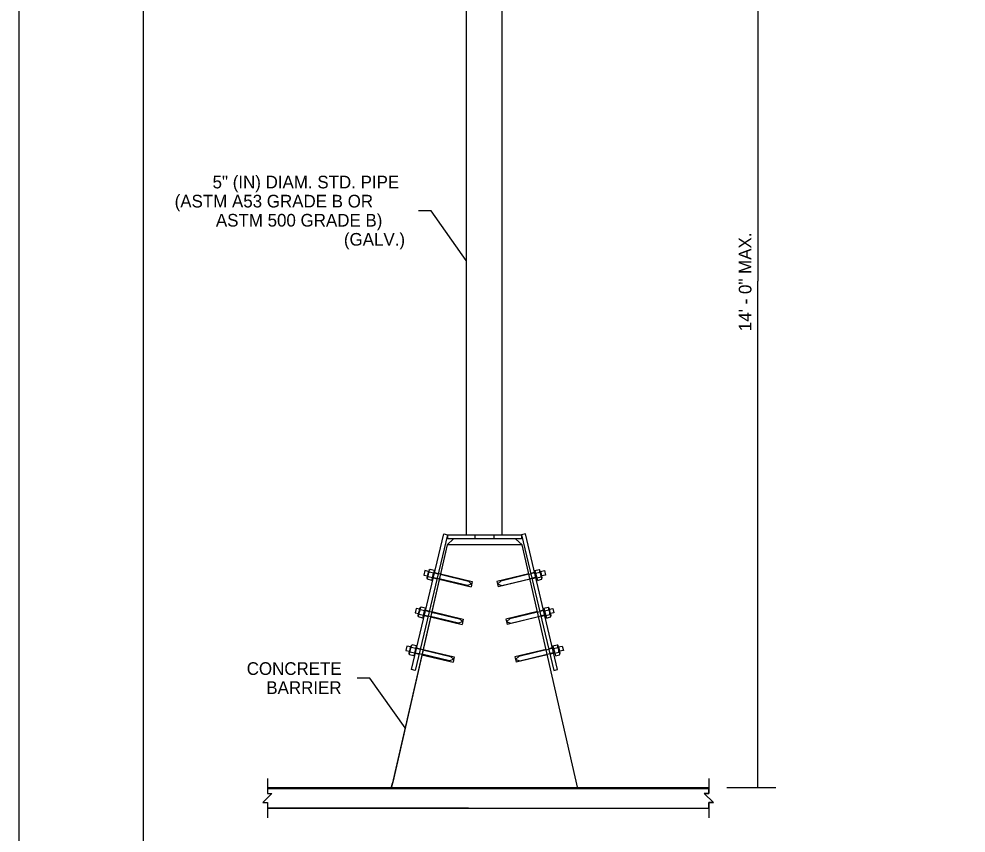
# Model space of a CAD drawing. Extents: x 99988 to 100172, y 99995 to 100047.
# Drawn here: x 99999.31 to 100004.55, y 100001.43 to 100005.94 of the extents above; entities that cross this region are included whole.
import ezdxf

# ---------------------------------------------------------------- set-up
doc = ezdxf.new("R2010")
doc.units = 0
for name, color, linetype in [('Level 1', 7, 'Continuous'), ('Level 10', 7, 'Continuous'), ('Level 12', 7, 'Continuous'), ('Level 15', 7, 'Continuous'), ('Level 18', 7, 'Continuous'), ('Level 20', 7, 'Continuous'), ('Level 8', 7, 'Continuous'), ('SH_GI_PlotLimits', 7, 'Continuous'), ('SH_GI_SheetBorder', 7, 'Continuous')]:
    doc.layers.add(name, color=color, linetype=linetype)

msp = doc.modelspace()

# ---------------------------------------------------------------- linework, layer by layer
at = {"layer": 'Level 1'}
msp.add_line((100000.6865, 100001.681), (100003.128, 100001.681), dxfattribs=at)
for points in [[(100001.7992, 100001.571), (100000.6865, 100001.571)], [(100000.6865, 100001.571), (100003.128, 100001.571)]]:
    msp.add_lwpolyline(points, dxfattribs=at)
at = {"layer": 'Level 10'}
for p, q in [((100001.7865, 100006.8371), (100001.7865, 100003.0807)), ((100001.9852, 100003.0795), (100001.9852, 100006.8371))]:
    msp.add_line(p, q, dxfattribs=at)
at = {"layer": 'Level 12'}
for p, q in [((100001.6841, 100003.0822), (100002.0912, 100003.0822)), ((100001.6841, 100003.0822), (100002.0912, 100003.0822)), ((100001.6841, 100003.0607), (100001.6841, 100003.0822)), ((100002.0912, 100003.0607), (100001.6841, 100003.0607)), ((100001.8341, 100003.0822), (100001.8341, 100003.0607)), ((100001.9412, 100003.0607), (100001.8341, 100003.0607)), ((100001.9412, 100003.0607), (100001.9412, 100003.0822)), ((100002.0912, 100003.0822), (100002.0912, 100003.0607))]:
    msp.add_line(p, q, dxfattribs=at)
for points in [[(100001.683, 100003.0834), (100001.5046, 100002.3333), (100001.4838, 100002.3382), (100001.6621, 100003.0884)], [(100002.0923, 100003.0834), (100002.2707, 100002.3333), (100002.2915, 100002.3382), (100002.1132, 100003.0884)]]:
    msp.add_lwpolyline(points, close=True, dxfattribs=at)
at = {"layer": 'Level 15'}
for p, q in [((100003.3984, 100007.2852), (100003.3984, 100004.4852)), ((100003.3984, 100001.6852), (100003.3984, 100004.4852)), ((100003.228, 100001.6852), (100003.4984, 100001.6852))]:
    msp.add_line(p, q, dxfattribs=at)
for points in [[(100001.7865, 100004.6), (100001.5917, 100004.8754), (100001.5217, 100004.8754)], [(100001.4482, 100002.0153), (100001.2534, 100002.2907), (100001.1834, 100002.2907)], [(100000.6865, 100001.7357), (100000.6865, 100001.6525), (100000.7118, 100001.6525), (100000.6612, 100001.602), (100000.6865, 100001.602), (100000.6865, 100001.5188)], [(100003.128, 100001.7357), (100003.128, 100001.6525), (100003.1027, 100001.6525), (100003.1532, 100001.602), (100003.128, 100001.602), (100003.128, 100001.5188)]]:
    msp.add_lwpolyline(points, dxfattribs=at)
at = {"layer": 'Level 18'}
for p, q in [((100001.8019, 100003.0822), (100001.9733, 100003.0822)), ((100001.968, 100003.0822), (100001.9733, 100003.0822)), ((100001.5572, 100002.8851), (100001.5514, 100002.8608)), ((100001.5514, 100002.8608), (100001.5721, 100002.8558)), ((100001.5782, 100002.8801), (100001.5572, 100002.8851)), ((100001.6001, 100002.8491), (100001.605, 100002.848)), ((100001.605, 100002.848), (100001.6258, 100002.843)), ((100001.6062, 100002.8734), (100001.6107, 100002.8723)), ((100001.6107, 100002.8723), (100001.6316, 100002.8674)), ((100001.6426, 100002.8647), (100001.6316, 100002.8674)), ((100001.6426, 100002.8647), (100001.7983, 100002.8277)), ((100002.1328, 100002.8647), (100001.9771, 100002.8277)), ((100002.1328, 100002.8647), (100002.1438, 100002.8674)), ((100002.1647, 100002.8723), (100002.1438, 100002.8674)), ((100002.1705, 100002.848), (100002.1496, 100002.843)), ((100002.1692, 100002.8734), (100002.1647, 100002.8723)), ((100002.1753, 100002.8491), (100002.1705, 100002.848)), ((100002.1972, 100002.8801), (100002.2183, 100002.8851)), ((100002.224, 100002.8608), (100002.2033, 100002.8558)), ((100002.2183, 100002.8851), (100002.224, 100002.8608)), ((100001.6258, 100002.843), (100001.6371, 100002.8404)), ((100001.7925, 100002.8034), (100001.6371, 100002.8404)), ((100001.8135, 100002.8099), (100001.7925, 100002.8034)), ((100001.7983, 100002.8277), (100001.8141, 100002.8124)), ((100001.9771, 100002.8277), (100001.9613, 100002.8124)), ((100001.9619, 100002.8099), (100001.9829, 100002.8034)), ((100001.9829, 100002.8034), (100002.1384, 100002.8404)), ((100002.1384, 100002.8404), (100002.1496, 100002.843)), ((100001.51, 100002.6762), (100001.5042, 100002.6519)), ((100001.5042, 100002.6519), (100001.5233, 100002.6473)), ((100001.5289, 100002.6717), (100001.51, 100002.6762)), ((100001.5505, 100002.6407), (100001.5554, 100002.6395)), ((100001.5554, 100002.6395), (100001.5762, 100002.6346)), ((100001.5566, 100002.6649), (100001.5612, 100002.6639)), ((100001.5612, 100002.6639), (100001.582, 100002.6589)), ((100001.5948, 100002.6559), (100001.582, 100002.6589)), ((100001.5948, 100002.6559), (100001.7488, 100002.6193)), ((100002.1806, 100002.6559), (100002.0267, 100002.6193)), ((100002.1806, 100002.6559), (100002.1934, 100002.6589)), ((100002.2142, 100002.6639), (100002.1934, 100002.6589)), ((100002.22, 100002.6395), (100002.1992, 100002.6346)), ((100002.2188, 100002.6649), (100002.2142, 100002.6639)), ((100002.2249, 100002.6407), (100002.22, 100002.6395)), ((100002.2465, 100002.6717), (100002.2654, 100002.6762)), ((100002.2712, 100002.6519), (100002.2522, 100002.6473)), ((100002.2654, 100002.6762), (100002.2712, 100002.6519)), ((100001.5762, 100002.6346), (100001.5892, 100002.6315)), ((100001.743, 100002.5949), (100001.5892, 100002.6315)), ((100001.764, 100002.6015), (100001.743, 100002.5949)), ((100001.7488, 100002.6193), (100001.7646, 100002.604)), ((100002.0267, 100002.6193), (100002.0108, 100002.604)), ((100002.0114, 100002.6015), (100002.0324, 100002.5949)), ((100002.0324, 100002.5949), (100002.1862, 100002.6315)), ((100002.1862, 100002.6315), (100002.1992, 100002.6346)), ((100001.458, 100002.4682), (100001.4522, 100002.4438)), ((100001.4522, 100002.4438), (100001.4729, 100002.4389)), ((100001.479, 100002.4632), (100001.458, 100002.4682)), ((100001.5006, 100002.4323), (100001.5056, 100002.4311)), ((100001.5056, 100002.4311), (100001.5264, 100002.4262)), ((100001.5069, 100002.4565), (100001.5114, 100002.4555)), ((100001.5114, 100002.4555), (100001.5322, 100002.4505)), ((100001.547, 100002.447), (100001.5322, 100002.4505)), ((100001.547, 100002.447), (100001.699, 100002.4109)), ((100002.2284, 100002.447), (100002.0765, 100002.4109)), ((100002.2284, 100002.447), (100002.2432, 100002.4505)), ((100002.264, 100002.4555), (100002.2432, 100002.4505)), ((100002.2698, 100002.4311), (100002.249, 100002.4262)), ((100002.2686, 100002.4565), (100002.264, 100002.4555)), ((100002.2748, 100002.4323), (100002.2698, 100002.4311)), ((100002.2964, 100002.4632), (100002.3174, 100002.4682)), ((100002.3232, 100002.4438), (100002.3025, 100002.4389)), ((100002.3174, 100002.4682), (100002.3232, 100002.4438)), ((100001.5264, 100002.4262), (100001.5414, 100002.4226)), ((100001.6932, 100002.3866), (100001.5414, 100002.4226)), ((100001.7142, 100002.3931), (100001.6932, 100002.3866)), ((100001.699, 100002.4109), (100001.7148, 100002.3956)), ((100002.0765, 100002.4109), (100002.0606, 100002.3956)), ((100002.0612, 100002.3931), (100002.0822, 100002.3866)), ((100002.0822, 100002.3866), (100002.234, 100002.4226)), ((100002.234, 100002.4226), (100002.249, 100002.4262))]:
    msp.add_line(p, q, dxfattribs=at)
for centre, start, end in [((100001.8131, 100002.8113), 287.2722, 45.9747), ((100001.9623, 100002.8113), 134.0253, 252.7278), ((100001.7635, 100002.6029), 287.2722, 45.9747), ((100002.0119, 100002.6029), 134.0253, 252.7278), ((100001.7137, 100002.3945), 287.2722, 45.9747), ((100002.0617, 100002.3945), 134.0253, 252.7278)]:
    msp.add_arc(centre, 0.0015, start, end, dxfattribs=at)
at = {"layer": 'Level 20'}
for p, q in [((100001.5697, 100002.8455), (100001.572, 100002.8545)), ((100001.599, 100002.8448), (100001.5757, 100002.8507)), ((100001.5858, 100002.8912), (100001.5796, 100002.8851)), ((100001.6058, 100002.8717), (100001.5825, 100002.8775)), ((100001.6091, 100002.8853), (100001.5859, 100002.8911)), ((100001.5989, 100002.8445), (100001.6058, 100002.8719)), ((100001.6058, 100002.8717), (100001.599, 100002.8448)), ((100001.6091, 100002.8853), (100001.6058, 100002.8717)), ((100001.6091, 100002.8854), (100001.6091, 100002.8853)), ((100001.6113, 100002.8747), (100001.6322, 100002.8698)), ((100001.6432, 100002.8672), (100001.8194, 100002.8253)), ((100002.1322, 100002.8672), (100001.956, 100002.8253)), ((100002.1641, 100002.8747), (100002.1433, 100002.8698)), ((100002.1663, 100002.8853), (100002.1895, 100002.8911)), ((100002.1663, 100002.8854), (100002.1664, 100002.8853)), ((100002.1663, 100002.8853), (100002.1697, 100002.8717)), ((100002.1765, 100002.8445), (100002.1696, 100002.8719)), ((100002.1697, 100002.8717), (100002.193, 100002.8775)), ((100002.1697, 100002.8717), (100002.1764, 100002.8448)), ((100002.1764, 100002.8448), (100002.1997, 100002.8507)), ((100002.1896, 100002.8912), (100002.1958, 100002.8851)), ((100002.2057, 100002.8455), (100002.2034, 100002.8545)), ((100001.5956, 100002.8313), (100001.5723, 100002.8371)), ((100001.599, 100002.8448), (100001.5956, 100002.8313)), ((100001.5956, 100002.8313), (100001.5989, 100002.8445)), ((100001.6044, 100002.8456), (100001.6252, 100002.8406)), ((100001.6365, 100002.8379), (100001.8125, 100002.7961)), ((100001.8194, 100002.8253), (100001.8125, 100002.7961)), ((100001.956, 100002.8253), (100001.9629, 100002.7961)), ((100002.1389, 100002.8379), (100001.9629, 100002.7961)), ((100002.171, 100002.8456), (100002.1502, 100002.8406)), ((100002.1764, 100002.8448), (100002.1798, 100002.8313)), ((100002.1798, 100002.8313), (100002.1765, 100002.8445)), ((100002.1798, 100002.8313), (100002.2031, 100002.8371)), ((100001.5202, 100002.6371), (100001.5224, 100002.6461)), ((100001.5495, 100002.6364), (100001.5262, 100002.6422)), ((100001.5362, 100002.6827), (100001.5301, 100002.6766)), ((100001.5562, 100002.6633), (100001.5329, 100002.6691)), ((100001.5596, 100002.6768), (100001.5363, 100002.6827)), ((100001.5494, 100002.636), (100001.5562, 100002.6634)), ((100001.5562, 100002.6633), (100001.5495, 100002.6364)), ((100001.5596, 100002.6768), (100001.5562, 100002.6633)), ((100001.5595, 100002.6769), (100001.5595, 100002.6768)), ((100001.5618, 100002.6663), (100001.5826, 100002.6613)), ((100001.5954, 100002.6583), (100001.7699, 100002.6168)), ((100002.18, 100002.6583), (100002.0056, 100002.6168)), ((100002.2137, 100002.6663), (100002.1928, 100002.6613)), ((100002.2158, 100002.6768), (100002.2391, 100002.6827)), ((100002.2158, 100002.6768), (100002.2192, 100002.6633)), ((100002.2159, 100002.6769), (100002.2159, 100002.6768)), ((100002.2192, 100002.6633), (100002.2425, 100002.6691)), ((100002.226, 100002.636), (100002.2192, 100002.6634)), ((100002.2192, 100002.6633), (100002.226, 100002.6364)), ((100002.226, 100002.6364), (100002.2492, 100002.6422)), ((100002.2392, 100002.6827), (100002.2454, 100002.6766)), ((100002.2553, 100002.6371), (100002.253, 100002.6461)), ((100001.5461, 100002.6228), (100001.5228, 100002.6287)), ((100001.5495, 100002.6364), (100001.5461, 100002.6228)), ((100001.5461, 100002.6228), (100001.5494, 100002.636)), ((100001.5548, 100002.6371), (100001.5757, 100002.6321)), ((100001.5887, 100002.6291), (100001.7629, 100002.5876)), ((100001.7699, 100002.6168), (100001.7629, 100002.5876)), ((100002.0056, 100002.6168), (100002.0125, 100002.5876)), ((100002.1867, 100002.6291), (100002.0125, 100002.5876)), ((100002.2206, 100002.6371), (100002.1998, 100002.6321)), ((100002.226, 100002.6364), (100002.2294, 100002.6228)), ((100002.2294, 100002.6228), (100002.226, 100002.636)), ((100002.2294, 100002.6228), (100002.2526, 100002.6287)), ((100001.4704, 100002.4287), (100001.4726, 100002.4377)), ((100001.4997, 100002.428), (100001.4764, 100002.4338)), ((100001.4793, 100002.4644), (100001.4803, 100002.4682)), ((100001.4864, 100002.4744), (100001.4803, 100002.4682)), ((100001.5064, 100002.4549), (100001.4831, 100002.4607)), ((100001.5098, 100002.4684), (100001.4865, 100002.4743)), ((100001.5064, 100002.4549), (100001.4997, 100002.428)), ((100001.505, 100002.4287), (100001.5259, 100002.4238)), ((100001.5098, 100002.4684), (100001.5064, 100002.4549)), ((100001.5097, 100002.4685), (100001.5097, 100002.4685)), ((100001.512, 100002.4579), (100001.5328, 100002.4529)), ((100001.5475, 100002.4494), (100001.7201, 100002.4084)), ((100002.2279, 100002.4494), (100002.0554, 100002.4084)), ((100002.2635, 100002.4579), (100002.2426, 100002.4529)), ((100002.2704, 100002.4287), (100002.2496, 100002.4238)), ((100002.2656, 100002.4684), (100002.2889, 100002.4743)), ((100002.2656, 100002.4684), (100002.269, 100002.4549)), ((100002.2657, 100002.4685), (100002.2657, 100002.4685)), ((100002.269, 100002.4549), (100002.2923, 100002.4607)), ((100002.269, 100002.4549), (100002.2758, 100002.428)), ((100002.2758, 100002.428), (100002.2991, 100002.4338)), ((100002.289, 100002.4744), (100002.2952, 100002.4682)), ((100002.2961, 100002.4644), (100002.2952, 100002.4682)), ((100002.3051, 100002.4287), (100002.3028, 100002.4377)), ((100002.3171, 100002.4694), (100002.3171, 100002.4694)), ((100001.4963, 100002.4144), (100001.473, 100002.4203)), ((100001.4997, 100002.428), (100001.4963, 100002.4144)), ((100001.5409, 100002.4202), (100001.7131, 100002.3792)), ((100001.7201, 100002.4084), (100001.7131, 100002.3792)), ((100002.0554, 100002.4084), (100002.0623, 100002.3792)), ((100002.2346, 100002.4202), (100002.0623, 100002.3792)), ((100002.2758, 100002.428), (100002.2792, 100002.4144)), ((100002.2792, 100002.4144), (100002.3024, 100002.4203))]:
    msp.add_line(p, q, dxfattribs=at)
msp.add_lwpolyline([(100001.7992, 100001.571), (100003.128, 100001.571), (100003.128, 100001.602), (100003.1532, 100001.602), (100003.1027, 100001.6525), (100003.128, 100001.6525), (100003.128, 100001.6835), (100002.8444, 100001.6835), (100002.6245, 100001.6835), (100002.2575, 100001.6835), (100001.5473, 100001.6835), (100001.1804, 100001.6835), (100001.0523, 100001.6835), (100000.6865, 100001.6835), (100000.6865, 100001.6525), (100000.7118, 100001.6525), (100000.6612, 100001.602), (100000.6865, 100001.602), (100000.6865, 100001.571), (100001.7992, 100001.571)], dxfattribs=at)
for points, degree in [([(100001.5723, 100002.8371), (100001.5716, 100002.8396), (100001.5713, 100002.8421), (100001.5724, 100002.8467), (100001.5738, 100002.8488), (100001.5757, 100002.8507)], 3), ([(100001.5723, 100002.8371), (100001.5716, 100002.8396), (100001.5713, 100002.8421), (100001.5724, 100002.8467), (100001.5738, 100002.8488), (100001.5757, 100002.8507)], 3), ([(100001.572, 100002.8545), (100001.572, 100002.8545), (100001.5787, 100002.8812), (100001.5796, 100002.8851), (100001.5787, 100002.8812), (100001.572, 100002.8545), (100001.572, 100002.8545)], 4), ([(100001.5757, 100002.8507), (100001.5755, 100002.8554), (100001.5758, 100002.86), (100001.5781, 100002.8692), (100001.58, 100002.8735), (100001.5825, 100002.8775)], 3), ([(100001.5825, 100002.8775), (100001.5817, 100002.8801), (100001.5814, 100002.8825), (100001.5826, 100002.8872), (100001.584, 100002.8892), (100001.5859, 100002.8911)], 3), ([(100001.5825, 100002.8775), (100001.5817, 100002.8801), (100001.5814, 100002.8825), (100001.5826, 100002.8872), (100001.584, 100002.8892), (100001.5859, 100002.8911)], 3), ([(100002.193, 100002.8775), (100002.1937, 100002.8801), (100002.194, 100002.8825), (100002.1929, 100002.8872), (100002.1914, 100002.8892), (100002.1895, 100002.8911)], 3), ([(100002.193, 100002.8775), (100002.1937, 100002.8801), (100002.194, 100002.8825), (100002.1929, 100002.8872), (100002.1914, 100002.8892), (100002.1895, 100002.8911)], 3), ([(100002.1997, 100002.8507), (100002.1999, 100002.8554), (100002.1996, 100002.86), (100002.1973, 100002.8692), (100002.1954, 100002.8735), (100002.193, 100002.8775)], 3), ([(100002.2034, 100002.8545), (100002.2034, 100002.8545), (100002.1968, 100002.8812), (100002.1958, 100002.8851), (100002.1968, 100002.8812), (100002.2034, 100002.8545), (100002.2034, 100002.8545)], 4), ([(100002.2031, 100002.8371), (100002.2039, 100002.8396), (100002.2042, 100002.8421), (100002.203, 100002.8467), (100002.2016, 100002.8488), (100002.1997, 100002.8507)], 3), ([(100002.2031, 100002.8371), (100002.2039, 100002.8396), (100002.2042, 100002.8421), (100002.203, 100002.8467), (100002.2016, 100002.8488), (100002.1997, 100002.8507)], 3), ([(100001.5722, 100002.8373), (100001.5714, 100002.84), (100001.5706, 100002.8428), (100001.5697, 100002.8455)], 2), ([(100002.2032, 100002.8373), (100002.204, 100002.84), (100002.2049, 100002.8428), (100002.2057, 100002.8455)], 2), ([(100001.5228, 100002.6287), (100001.522, 100002.6312), (100001.5217, 100002.6337), (100001.5229, 100002.6383), (100001.5243, 100002.6403), (100001.5262, 100002.6422)], 3), ([(100001.5228, 100002.6287), (100001.522, 100002.6312), (100001.5217, 100002.6337), (100001.5229, 100002.6383), (100001.5243, 100002.6403), (100001.5262, 100002.6422)], 3), ([(100001.5224, 100002.6461), (100001.5224, 100002.6461), (100001.5253, 100002.6578), (100001.5301, 100002.6766)], 3), ([(100001.5262, 100002.6422), (100001.526, 100002.6469), (100001.5262, 100002.6516), (100001.5285, 100002.6607), (100001.5305, 100002.665), (100001.5329, 100002.6691)], 3), ([(100001.5266, 100002.6627), (100001.5266, 100002.6626), (100001.5266, 100002.6626), (100001.5265, 100002.6626)], 3), ([(100001.5329, 100002.6691), (100001.5321, 100002.6716), (100001.5318, 100002.6741), (100001.533, 100002.6787), (100001.5344, 100002.6808), (100001.5363, 100002.6827)], 3), ([(100001.5329, 100002.6691), (100001.5321, 100002.6716), (100001.5318, 100002.6741), (100001.533, 100002.6787), (100001.5344, 100002.6808), (100001.5363, 100002.6827)], 3), ([(100002.2425, 100002.6691), (100002.2433, 100002.6716), (100002.2436, 100002.6741), (100002.2424, 100002.6787), (100002.241, 100002.6808), (100002.2391, 100002.6827)], 3), ([(100002.2425, 100002.6691), (100002.2433, 100002.6716), (100002.2436, 100002.6741), (100002.2424, 100002.6787), (100002.241, 100002.6808), (100002.2391, 100002.6827)], 3), ([(100002.2492, 100002.6422), (100002.2495, 100002.6469), (100002.2492, 100002.6516), (100002.2469, 100002.6607), (100002.2449, 100002.665), (100002.2425, 100002.6691)], 3), ([(100002.253, 100002.6461), (100002.253, 100002.6461), (100002.2501, 100002.6578), (100002.2454, 100002.6766)], 3), ([(100002.2488, 100002.6627), (100002.2489, 100002.6626), (100002.2489, 100002.6626), (100002.2489, 100002.6626)], 3), ([(100002.2526, 100002.6287), (100002.2534, 100002.6312), (100002.2537, 100002.6337), (100002.2526, 100002.6383), (100002.2511, 100002.6403), (100002.2492, 100002.6422)], 3), ([(100002.2526, 100002.6287), (100002.2534, 100002.6312), (100002.2537, 100002.6337), (100002.2526, 100002.6383), (100002.2511, 100002.6403), (100002.2492, 100002.6422)], 3), ([(100001.5227, 100002.6289), (100001.5218, 100002.6316), (100001.521, 100002.6343), (100001.5202, 100002.6371)], 2), ([(100002.2527, 100002.6289), (100002.2536, 100002.6316), (100002.2544, 100002.6343), (100002.2553, 100002.6371)], 2), ([(100001.4729, 100002.4205), (100001.472, 100002.4232), (100001.4712, 100002.4259), (100001.4704, 100002.4287)], 2), ([(100001.473, 100002.4203), (100001.4722, 100002.4228), (100001.4719, 100002.4253), (100001.473, 100002.4299), (100001.4745, 100002.4319), (100001.4764, 100002.4338)], 3), ([(100001.473, 100002.4203), (100001.4722, 100002.4228), (100001.4719, 100002.4253), (100001.473, 100002.4299), (100001.4745, 100002.4319), (100001.4764, 100002.4338)], 3), ([(100001.4726, 100002.4377), (100001.4726, 100002.4377), (100001.4793, 100002.4644), (100001.4793, 100002.4644), (100001.4793, 100002.4644), (100001.4726, 100002.4377), (100001.4726, 100002.4377)], 4), ([(100001.4764, 100002.4338), (100001.4761, 100002.4385), (100001.4764, 100002.4432), (100001.4787, 100002.4524), (100001.4807, 100002.4567), (100001.4831, 100002.4607)], 3), ([(100001.4831, 100002.4607), (100001.4823, 100002.4633), (100001.482, 100002.4657), (100001.4832, 100002.4703), (100001.4846, 100002.4724), (100001.4865, 100002.4743)], 3), ([(100001.4831, 100002.4607), (100001.4823, 100002.4633), (100001.482, 100002.4657), (100001.4832, 100002.4703), (100001.4846, 100002.4724), (100001.4865, 100002.4743)], 3), ([(100002.2923, 100002.4607), (100002.2931, 100002.4633), (100002.2934, 100002.4657), (100002.2922, 100002.4703), (100002.2908, 100002.4724), (100002.2889, 100002.4743)], 3), ([(100002.2923, 100002.4607), (100002.2931, 100002.4633), (100002.2934, 100002.4657), (100002.2922, 100002.4703), (100002.2908, 100002.4724), (100002.2889, 100002.4743)], 3), ([(100002.2991, 100002.4338), (100002.2993, 100002.4385), (100002.299, 100002.4432), (100002.2967, 100002.4524), (100002.2947, 100002.4567), (100002.2923, 100002.4607)], 3), ([(100002.3028, 100002.4377), (100002.3028, 100002.4377), (100002.2961, 100002.4644), (100002.2961, 100002.4644), (100002.2961, 100002.4644), (100002.3028, 100002.4377), (100002.3028, 100002.4377)], 4), ([(100002.3024, 100002.4203), (100002.3032, 100002.4228), (100002.3035, 100002.4253), (100002.3024, 100002.4299), (100002.3009, 100002.4319), (100002.2991, 100002.4338)], 3), ([(100002.3024, 100002.4203), (100002.3032, 100002.4228), (100002.3035, 100002.4253), (100002.3024, 100002.4299), (100002.3009, 100002.4319), (100002.2991, 100002.4338)], 3), ([(100002.3025, 100002.4205), (100002.3034, 100002.4232), (100002.3042, 100002.4259), (100002.3051, 100002.4287)], 2)]:
    msp.add_open_spline(points, degree=degree, dxfattribs=at)
at = {"layer": 'Level 8'}
for p, q in [((100001.7163, 100003.0605), (100001.6802, 100003.0286)), ((100002.0591, 100003.0605), (100001.7163, 100003.0605)), ((100002.0953, 100003.0286), (100002.0591, 100003.0605)), ((100001.6802, 100003.0286), (100001.3716, 100001.681)), ((100002.0953, 100003.0286), (100001.6802, 100003.0286)), ((100002.0759, 100003.0456), (100002.0759, 100003.0453)), ((100001.3735, 100001.6892), (100001.3781, 100001.7092)), ((100001.3794, 100001.7152), (100001.3781, 100001.7092))]:
    msp.add_line(p, q, dxfattribs=at)
msp.add_lwpolyline([(100001.6802, 100003.0286), (100001.3794, 100001.7152), (100001.3781, 100001.7092), (100001.3735, 100001.6892), (100001.3716, 100001.681), (100002.4038, 100001.681), (100002.0953, 100003.0286), (100002.0759, 100003.0456), (100002.0591, 100003.0605), (100001.7163, 100003.0605), (100001.6802, 100003.0286)], dxfattribs=at)
at = {"layer": 'SH_GI_PlotLimits'}
msp.add_lwpolyline([(99999.3125, 99999.9375), (100015.8125, 99999.9375), (100015.8125, 100010.4375), (99999.3125, 100010.4375)], close=True, dxfattribs=at)
at = {"layer": 'SH_GI_SheetBorder'}
msp.add_line((100000, 100010.375), (100000, 100000), dxfattribs=at)

# ---------------------------------------------------------------- texts
at = {"layer": 'Level 20'}
for s, p in [('5" (IN) DIAM. STD. PIPE', (100000.3834, 100004.9988)), ('(ASTM A53 GRADE B OR', (100000.1735, 100004.8932)), ('ASTM 500 GRADE B)', (100000.4017, 100004.7876)), ('(GALV.)', (100001.1097, 100004.6821)), ('CONCRETE', (100000.5721, 100002.3085)), ('BARRIER', (100000.6806, 100002.203))]:
    msp.add_text(s, height=0.07, dxfattribs=at).set_placement(p)
msp.add_text('14\' - 0" MAX.', height=0.07, rotation=90, dxfattribs=at).set_placement((100003.3634, 100004.2094))

doc.saveas('drawing.dxf')
